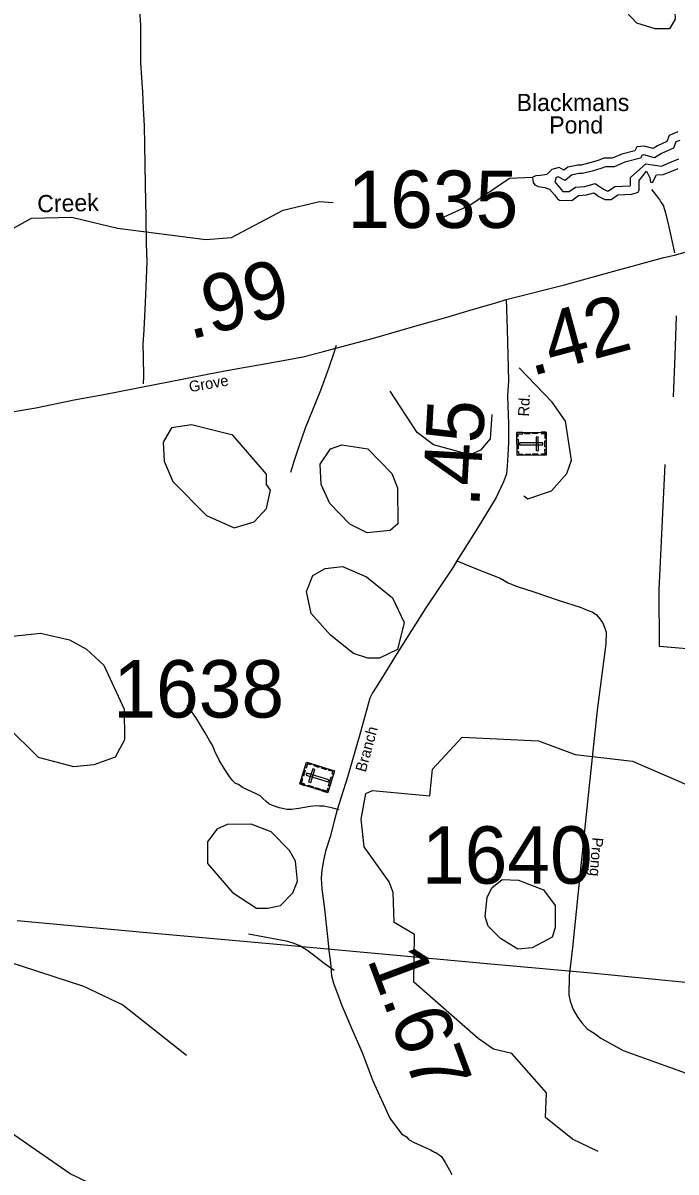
# Model space of a CAD drawing. Extents: x 2093524 to 2270757, y 289120 to 570408.
# Drawn here: x 2165044 to 2170729, y 536363 to 546370 of the extents above; entities that cross this region are included whole.
import ezdxf

# ---------------------------------------------------------------- set-up
doc = ezdxf.new("R2010")
doc.units = 0
for name, color, linetype in [('Exist Cultural Cemetery CELL', 7, 'Continuous'), ('Exist Hydrographic Buffer Line', 7, 'Continuous'), ('Exist Hydrographic Creek Single Shore', 7, 'Continuous'), ('Exist Hydrographic Creek Single Shore Label', 7, 'Continuous'), ('Exist Hydrographic Misc Water Feature', 7, 'Continuous'), ('Exist Hydrographic Pond Over 1500 Sq Ft', 7, 'Continuous'), ('Exist Hydrographic Pond Over 1500 Sq Ft Label', 7, 'Continuous'), ('Exist Hydrographic Pond Under 1500 Sq Ft', 7, 'Continuous'), ('Exist Road Non-System Type 51', 7, 'Continuous'), ('Exist Road Secondary Mileage Hundredths English Label', 7, 'Continuous'), ('Exist Road Secondary Type 51 Attributed', 7, 'Continuous'), ('Exist Road Secondary Type 51 Label', 7, 'Continuous'), ('Exist Road Secondary Type 51 Number Label', 7, 'Continuous'), ('Exist Utilities Telephone Line', 7, 'Continuous')]:
    doc.layers.add(name, color=color, linetype=linetype)

msp = doc.modelspace()

# ---------------------------------------------------------------- linework, layer by layer
at = {"layer": 'Exist Cultural Cemetery CELL'}
for points in [[(2169598, 542806), (2169600, 542607), (2169345, 542604), (2169343, 542803)], [(2169344, 542770), (2169355, 542770), (2169355, 542792), (2169395, 542793), (2169395, 542804), (2169343, 542803)], [(2169413, 542804), (2169457, 542805), (2169457, 542793), (2169413, 542793)], [(2169480, 542805), (2169524, 542805), (2169524, 542794), (2169481, 542794)], [(2169555, 542806), (2169555, 542794), (2169587, 542795), (2169587, 542754), (2169599, 542754), (2169598, 542806)], [(2169355, 542746), (2169356, 542661), (2169345, 542661), (2169344, 542746)], [(2169570, 542697), (2169570, 542715), (2169367, 542713), (2169367, 542695)], [(2169530, 542765), (2169512, 542764), (2169513, 542647), (2169532, 542647)], [(2169599, 542732), (2169599, 542680), (2169588, 542680), (2169587, 542732)], [(2169345, 542637), (2169357, 542638), (2169357, 542616), (2169397, 542616), (2169397, 542605), (2169345, 542604)], [(2169418, 542616), (2169461, 542617), (2169461, 542606), (2169418, 542605)], [(2169484, 542617), (2169527, 542618), (2169527, 542606), (2169484, 542606)], [(2169557, 542607), (2169557, 542618), (2169589, 542618), (2169588, 542659), (2169599, 542659), (2169600, 542607)], [(2167454, 539743), (2167513, 539933), (2167756, 539857), (2167697, 539667)], [(2167555, 539920), (2167551, 539909), (2167521, 539919), (2167508, 539880), (2167498, 539883), (2167513, 539933)], [(2167621, 539887), (2167580, 539900), (2167583, 539911), (2167624, 539898)], [(2167684, 539867), (2167643, 539880), (2167646, 539891), (2167687, 539878)], [(2167495, 539730), (2167499, 539741), (2167468, 539750), (2167480, 539789), (2167469, 539792), (2167454, 539743)], [(2167476, 539813), (2167491, 539863), (2167502, 539860), (2167487, 539810)], [(2167514, 539838), (2167509, 539820), (2167702, 539760), (2167708, 539778)], [(2167531, 539761), (2167549, 539756), (2167584, 539868), (2167566, 539874)], [(2167746, 539825), (2167735, 539829), (2167742, 539850), (2167703, 539862), (2167707, 539872), (2167756, 539857)], [(2167703, 539725), (2167728, 539806), (2167739, 539803), (2167714, 539722)], [(2167566, 539708), (2167525, 539721), (2167528, 539731), (2167569, 539719)], [(2167630, 539688), (2167589, 539701), (2167592, 539711), (2167633, 539698)], [(2167707, 539698), (2167696, 539702), (2167689, 539681), (2167651, 539693), (2167647, 539682), (2167697, 539667)]]:
    msp.add_lwpolyline(points, close=True, dxfattribs=at)
at = {"layer": 'Exist Hydrographic Buffer Line'}
msp.add_lwpolyline([(2170762, 545348), (2170729, 545335), (2170708, 545281), (2170604, 545234), (2170543, 545196), (2170448, 545222), (2170435, 545220), (2170419, 545194), (2170283, 545158), (2170191, 545118), (2170116, 545118), (2170076, 545102), (2169998, 545079), (2169915, 545058), (2169882, 545058), (2169820, 545045), (2169763, 544999), (2169704, 545030), (2169687, 545025), (2169674, 544988), (2169729, 544920), (2169744, 544902), (2169798, 544901), (2169855, 544940), (2169936, 544946), (2170027, 544972), (2170097, 544923), (2170128, 544907), (2170142, 544907), (2170198, 544946), (2170330, 544953), (2170334, 544954), (2170334, 545024), (2170468, 545144), (2170603, 545124), (2170677, 545154), (2170753, 545188)], dxfattribs=at)
at = {"layer": 'Exist Hydrographic Creek Single Shore'}
for points in [[(2168711, 544681), (2168933, 544783), (2169281, 545019), (2169481, 545028)], [(2164703, 544442), (2165118, 544670), (2165468, 544679), (2165868, 544582), (2166635, 544485), (2166860, 544503), (2167308, 544740), (2167625, 544816), (2167744, 544808)], [(2171028, 540903), (2170587, 540941), (2170584, 541433), (2170636, 542525)], [(2170051, 536543), (2169828, 536650), (2169593, 536838), (2169601, 537054), (2169299, 537395), (2169140, 537434), (2169007, 537526), (2168446, 538016), (2168452, 538432), (2168276, 538537), (2168266, 538797), (2168232, 538889), (2168014, 539196), (2167988, 539436), (2168028, 539661), (2168086, 539686), (2168586, 539640), (2168610, 539872), (2168867, 540149), (2169533, 540119), (2169851, 539998), (2170351, 539942), (2170935, 539688)]]:
    msp.add_lwpolyline(points, dxfattribs=at)
at = {"layer": 'Exist Hydrographic Misc Water Feature'}
for points in [[(2169405, 542251), (2169438, 542227), (2169646, 542295), (2169779, 542447), (2169820, 542564), (2169768, 542903), (2169650, 543069), (2169365, 543367)], [(2169126, 542959), (2169111, 542749), (2169028, 542649), (2168936, 542608), (2168619, 542696), (2168477, 542804), (2168242, 543163)], [(2166065, 536168), (2166016, 536126), (2165690, 536234), (2165456, 536347), (2164745, 536837), (2164418, 537218), (2164292, 537568), (2164298, 537801), (2164463, 538103), (2164746, 538202), (2164921, 538195), (2165572, 537982), (2165914, 537818), (2166467, 537380)]]:
    msp.add_lwpolyline(points, dxfattribs=at)
at = {"layer": 'Exist Hydrographic Pond Over 1500 Sq Ft'}
msp.add_lwpolyline([(2170746, 545423), (2170671, 545391), (2170649, 545337), (2170568, 545300), (2170531, 545277), (2170453, 545298), (2170388, 545290), (2170370, 545258), (2170258, 545229), (2170175, 545193), (2170102, 545193), (2170052, 545173), (2169979, 545151), (2169905, 545133), (2169874, 545133), (2169787, 545115), (2169754, 545088), (2169713, 545110), (2169649, 545093), (2169604, 545051), (2169550, 545041), (2169508, 545038), (2169481, 545028), (2169485, 544982), (2169501, 544960), (2169528, 544945), (2169588, 544937), (2169629, 544923), (2169671, 544872), (2169698, 544840), (2169716, 544827), (2169821, 544825), (2169880, 544867), (2169949, 544872), (2170013, 544890), (2170058, 544859), (2170110, 544832), (2170165, 544832), (2170223, 544872), (2170344, 544878), (2170399, 544897), (2170409, 544915), (2170409, 544998), (2170472, 545080), (2170501, 545021), (2170506, 544985), (2170524, 544980), (2170560, 545048), (2170619, 545050), (2170707, 545085), (2170747, 545103)], dxfattribs=at)
at = {"layer": 'Exist Hydrographic Pond Under 1500 Sq Ft'}
for points in [[(2170547, 546318), (2170389, 546367), (2170196, 546574), (2170186, 546807), (2170236, 546885), (2170311, 546900), (2170569, 546836), (2170712, 546597), (2170722, 546403), (2170672, 546319), (2170547, 546318)], [(2166883, 541973), (2167058, 542025), (2167165, 542141), (2167198, 542301), (2167164, 542351), (2167164, 542440), (2166870, 542780), (2166512, 542870), (2166337, 542844), (2166263, 542720), (2166272, 542553), (2166348, 542378), (2166641, 542080), (2166883, 541973)], [(2168041, 541930), (2167891, 542005), (2167715, 542186), (2167639, 542352), (2167630, 542529), (2167721, 542662), (2167821, 542696), (2168046, 542662), (2168255, 542447), (2168306, 542322), (2168308, 542007), (2168241, 541949), (2168041, 541930)], [(2168047, 540838), (2167922, 540880), (2167722, 541038), (2167554, 541228), (2167511, 541419), (2167568, 541559), (2167676, 541619), (2167826, 541636), (2168035, 541547), (2168261, 541365), (2168362, 541150), (2168305, 540915), (2168147, 540839), (2168047, 540838)], [(2165487, 539892), (2165178, 539974), (2164902, 540245), (2164776, 540461), (2164776, 540504), (2164725, 540570), (2164732, 540744), (2164831, 540955), (2164956, 541031), (2165197, 541056), (2165448, 540998), (2165598, 540917), (2165749, 540776), (2165926, 540395), (2165927, 540126), (2165845, 539977), (2165662, 539908), (2165487, 539892)], [(2167177, 538661), (2167285, 538685), (2167392, 538794), (2167434, 538895), (2167416, 539069), (2167365, 539162), (2167206, 539326), (2167031, 539392), (2166823, 539390), (2166731, 539349), (2166649, 539239), (2166650, 539049), (2166868, 538798), (2167077, 538660), (2167177, 538661)], [(2169353, 538305), (2169202, 538397), (2169093, 538504), (2169068, 538587), (2169084, 538754), (2169125, 538838), (2169216, 538912), (2169358, 538906), (2169575, 538822), (2169676, 538683), (2169677, 538489), (2169652, 538408), (2169478, 538316), (2169353, 538305)]]:
    msp.add_lwpolyline(points, dxfattribs=at)
at = {"layer": 'Exist Road Non-System Type 51'}
for points in [[(2166063, 546617), (2166062, 546439), (2166066, 546348), (2166067, 546023), (2166083, 545767), (2166091, 545629), (2166098, 545473), (2166102, 545313), (2166109, 544957), (2166113, 544681), (2166116, 544447), (2166121, 544289), (2166116, 544145), (2166108, 543937), (2166096, 543699), (2166088, 543573), (2166089, 543461), (2166092, 543295), (2166089, 543227)], [(2170515, 544921), (2170533, 544899), (2170558, 544867), (2170586, 544833), (2170597, 544809), (2170617, 544783), (2170637, 544716), (2170668, 544596), (2170717, 544368)], [(2170731, 543821), (2170719, 543467), (2170706, 543115)], [(2167771, 543562), (2167747, 543488), (2167704, 543361), (2167634, 543169), (2167501, 542840), (2167472, 542758), (2167439, 542665), (2167405, 542561), (2167374, 542455)], [(2167798, 539517), (2167741, 539533), (2167663, 539550), (2167625, 539549), (2167599, 539551), (2167545, 539547), (2167445, 539528), (2167381, 539519), (2167345, 539519), (2167275, 539535), (2167217, 539556), (2167183, 539569), (2167161, 539591), (2167128, 539619), (2167108, 539639), (2167068, 539660), (2166960, 539709), (2166921, 539737), (2166895, 539747), (2166867, 539773), (2166843, 539808), (2166802, 539870), (2166751, 539951), (2166711, 540033), (2166696, 540075), (2166668, 540121), (2166631, 540188), (2166548, 540322), (2166473, 540429)], [(2167753, 538119), (2167666, 538180), (2167585, 538243), (2167515, 538295), (2167454, 538332), (2167404, 538354), (2167350, 538371), (2167256, 538388), (2167007, 538434)]]:
    msp.add_lwpolyline(points, dxfattribs=at)
at = {"layer": 'Exist Road Secondary Type 51 Attributed'}
for points in [[(2169251, 543962), (2169758, 544091), (2170156, 544201), (2170623, 544327), (2170717, 544348), (2171044, 544441), (2171309, 544507), (2171365, 544520), (2171401, 544526)], [(2164898, 542974), (2165156, 543018), (2165490, 543087), (2165747, 543135), (2166015, 543188), (2166087, 543202), (2166431, 543267), (2166666, 543315), (2166834, 543345), (2167148, 543401), (2167341, 543436), (2167481, 543463), (2167659, 543508), (2167769, 543537), (2168096, 543624), (2168296, 543682), (2168497, 543742), (2168725, 543804), (2168966, 543878), (2169160, 543932), (2169251, 543962)], [(2169251, 543962), (2169260, 543703), (2169271, 543253), (2169262, 543123), (2169270, 542877), (2169272, 542717), (2169265, 542605), (2169260, 542513), (2169253, 542445), (2169227, 542375), (2169164, 542238), (2169001, 541969), (2168821, 541685)], [(2168821, 541685), (2168788, 541632), (2168552, 541276), (2168303, 540883), (2168177, 540678), (2168112, 540578), (2168087, 540536), (2168065, 540490), (2168049, 540437), (2167982, 540193), (2167869, 539802), (2167780, 539517), (2167753, 539419), (2167718, 539282), (2167677, 539158), (2167658, 539062), (2167647, 538988), (2167641, 538922), (2167646, 538830), (2167670, 538654), (2167696, 538412), (2167711, 538269), (2167716, 538229), (2167722, 538185), (2167727, 538111), (2167730, 538072), (2167748, 538008), (2167819, 537812), (2167914, 537595), (2167998, 537404), (2168090, 537157), (2168239, 536831), (2168339, 536697), (2168382, 536669), (2168400, 536649), (2168406, 536643), (2168445, 536623), (2168592, 536555), (2168627, 536537), (2168638, 536532), (2168688, 536498), (2168720, 536445), (2168755, 536384), (2168777, 536341)], [(2168821, 541685), (2168998, 541612), (2169197, 541534), (2169269, 541495), (2169338, 541465), (2169492, 541415), (2169703, 541342), (2169904, 541280), (2169956, 541255), (2170000, 541241), (2170036, 541215), (2170067, 541182), (2170089, 541150), (2170107, 541108), (2170122, 541064), (2170119, 540964), (2170042, 540384), (2169963, 539617), (2169895, 538974), (2169827, 538318), (2169799, 538072), (2169796, 537907), (2169807, 537852), (2169834, 537779), (2169875, 537708), (2169910, 537663), (2169957, 537611), (2170027, 537568), (2170074, 537529), (2170269, 537420), (2170994, 537161)]]:
    msp.add_lwpolyline(points, dxfattribs=at)
at = {"layer": 'Exist Utilities Telephone Line'}
msp.add_lwpolyline([(2177777, 537943), (2177246, 537949), (2176642, 537931), (2175937, 537882), (2174279, 537768), (2173972, 537749), (2173856, 537741), (2173687, 537752), (2173095, 537806), (2171339, 537962), (2169990, 538094), (2169149, 538169), (2167254, 538344), (2166122, 538446), (2164994, 538550)], dxfattribs=at)

# ---------------------------------------------------------------- texts
at = {"layer": 'Exist Hydrographic Creek Single Shore Label'}
msp.add_text('Creek', height=150, rotation=1.5269, dxfattribs=at).set_placement((2165170, 544720))
at = {"layer": 'Exist Hydrographic Pond Over 1500 Sq Ft Label'}
for s, p in [('Blackmans', (2169342, 545603)), ('Pond', (2169626, 545407))]:
    msp.add_text(s, height=150, dxfattribs=at).set_placement(p)
at = {"layer": 'Exist Road Secondary Mileage Hundredths English Label'}
for s, rotation, p in [('.99', 14.4248, (2166497, 543611)), ('.42', 15.143, (2169470, 543293)), ('.45', 86.8081, (2169016, 542147)), ('1.67', 290.5474, (2168038, 538219))]:
    msp.add_text(s, height=500, rotation=rotation, dxfattribs=at).set_placement(p)
at = {"layer": 'Exist Road Secondary Type 51 Label'}
for s, rotation, p in [('Grove', 9.9392, (2166498, 543154)), ('Rd.', 86.8081, (2169448, 542941)), ('Branch', 74.4865, (2168027, 539840)), ('Prong', 265.5469, (2170002, 539280))]:
    msp.add_text(s, height=95, rotation=rotation, dxfattribs=at).set_placement(p)
at = {"layer": 'Exist Road Secondary Type 51 Number Label'}
for s, p in [('1635', (2167869, 544585)), ('1638', (2165830, 540321)), ('1640', (2168517, 538874))]:
    msp.add_text(s, height=500, dxfattribs=at).set_placement(p)

doc.saveas('drawing.dxf')
